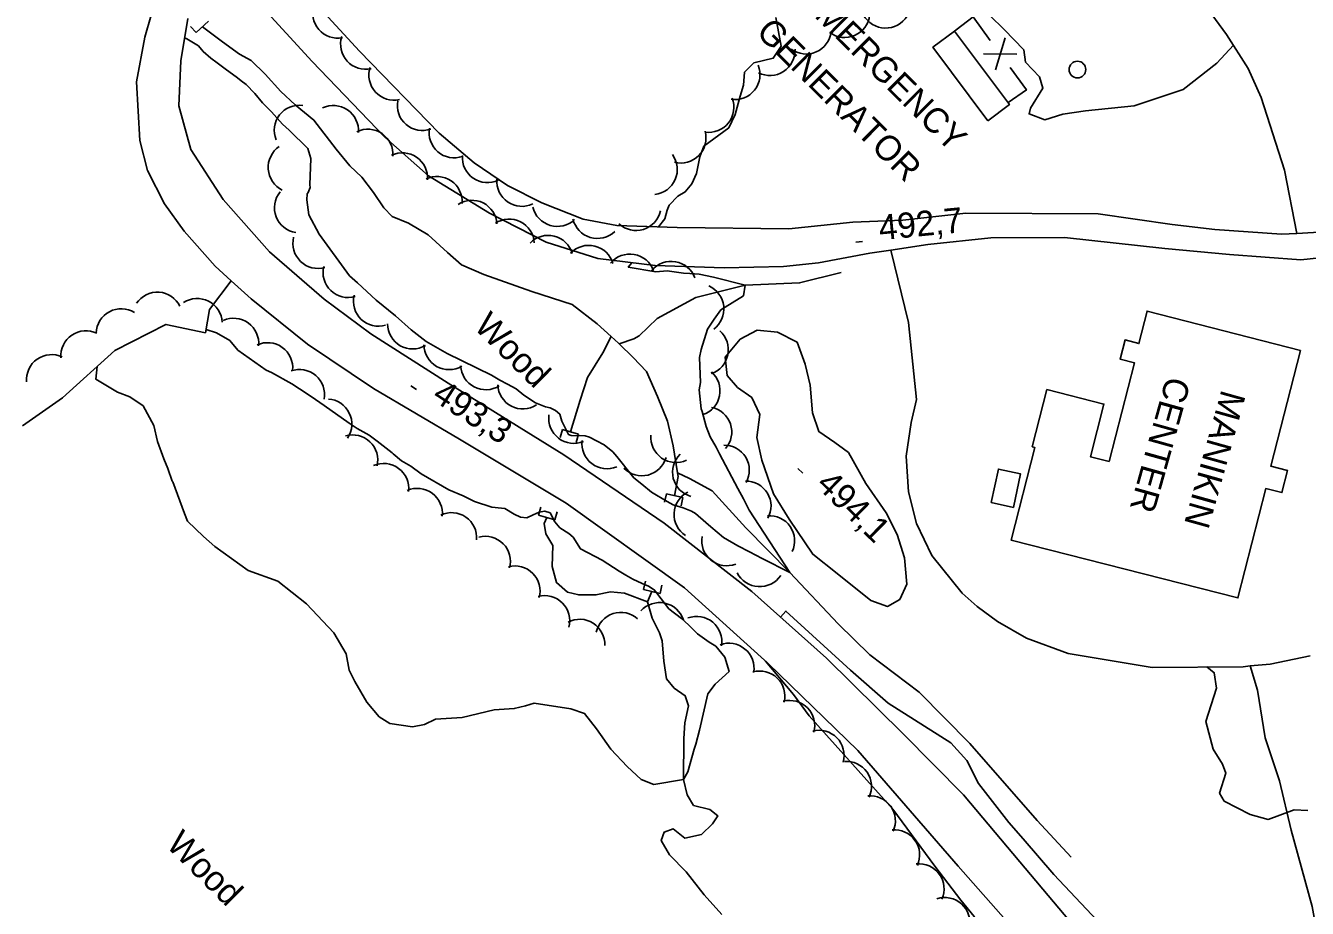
# Model space of a CAD drawing. Extents: x 642515 to 647219, y 6080136 to 6084356.
# Drawn here: x 643425.9 to 643579, y 6081671 to 6081776.4 of the extents above; entities that cross this region are included whole.
import ezdxf

# ---------------------------------------------------------------- set-up
doc = ezdxf.new("R2010")
doc.units = 0
for name, color, linetype in [('Level 19', 7, 'Continuous'), ('Level 2', 7, 'Continuous'), ('Level 21', 7, 'Continuous'), ('Level 22', 7, 'Continuous'), ('Level 26', 7, 'Continuous'), ('Level 3', 7, 'Continuous'), ('Level 31', 7, 'Continuous'), ('Level 36', 7, 'Continuous'), ('Level 37', 7, 'Continuous'), ('Level 4', 7, 'Continuous'), ('Level 44', 7, 'Continuous'), ('Level 52', 7, 'Continuous'), ('Level 57', 7, 'Continuous')]:
    doc.layers.add(name, color=color, linetype=linetype)

msp = doc.modelspace()

# ---------------------------------------------------------------- linework, layer by layer
at = {"layer": 'Level 19'}
msp.add_lwpolyline([(643577.69, 6081751.6), (643576.22, 6081759.16), (643573.43, 6081767.8), (643571.87, 6081771.28), (643569.31, 6081775.34), (643565.9, 6081779.99)], dxfattribs=at)
at = {"layer": 'Level 2'}
for points in [[(643570.12, 6081774.05), (643568.16, 6081771.91), (643564.14, 6081768.78), (643558.27, 6081766.82), (643552.46, 6081766.23), (643549.75, 6081765.81), (643547.58, 6081765.14), (643545.72, 6081765.86), (643545.88, 6081766.55), (643547.37, 6081768.95), (643546.96, 6081770.29), (643545.31, 6081772.04), (643545.09, 6081773.52), (643542.76, 6081775.94), (643541.04, 6081777.6), (643540.97, 6081780.46), (643542.26, 6081782.88), (643544.34, 6081785.52), (643547.63, 6081786.94), (643551.42, 6081787.48), (643553.06, 6081788.84), (643553.98, 6081790.75), (643552.03, 6081792.84), (643552.04, 6081793.47)], [(643515.48, 6081777.35), (643516.11, 6081773.93), (643515.16, 6081772.5), (643512.86, 6081771.95), (643511.73, 6081770.83), (643511.6, 6081769.29), (643511.2, 6081767.98), (643510.63, 6081765.77), (643509.85, 6081764.2), (643506.86, 6081761.99), (643506.38, 6081760.75), (643505.99, 6081758.76), (643505.43, 6081757.51), (643504.65, 6081756.54), (643503.76, 6081756.04), (643502.75, 6081754.96), (643502.51, 6081754.35), (643502.21, 6081753.32), (643501.48, 6081752.36)], [(643505.87, 6081718.17), (643505.41, 6081718.42), (643504.42, 6081718.84), (643503.23, 6081719.2), (643502.51, 6081719.6), (643500.63, 6081720.72), (643499.48, 6081721.65), (643498.5, 6081722.43), (643496.48, 6081724.95), (643496, 6081725.52), (643494.98, 6081726.34), (643494.06, 6081726.84), (643493.23, 6081727.27), (643492.69, 6081727.44), (643491.04, 6081727.45), (643490.71, 6081727.59), (643489.92, 6081729.18), (643489.66, 6081730.01), (643489.15, 6081730.46), (643488.52, 6081730.78), (643487.95, 6081730.9), (643486.76, 6081731.35), (643485.4, 6081732.3), (643484.47, 6081733.05), (643483.43, 6081733.58), (643482.51, 6081734.08), (643481.5, 6081734.66), (643476.22, 6081737.25), (643473.71, 6081738.69), (643471.92, 6081740.1), (643470.04, 6081741.75), (643467.75, 6081743.61), (643465.51, 6081745.71), (643464.57, 6081746.53), (643464.57, 6081746.53), (643464.57, 6081746.53), (643460.93, 6081751.51), (643459.7, 6081753.81), (643459.47, 6081755.6), (643459.5, 6081756.33), (643459.62, 6081756.46), (643459.86, 6081757.08), (643459.84, 6081757.4), (643459.96, 6081760.55), (643459.57, 6081761.73), (643457.34, 6081763.93), (643456.54, 6081764.65), (643455.24, 6081766.1), (643455.07, 6081766.25), (643454.17, 6081767.2), (643453.26, 6081768.31), (643452.23, 6081769.38), (643451.64, 6081769.82), (643451.18, 6081770.16), (643449.7, 6081771.24), (643448.74, 6081771.94), (643448.02, 6081772.5), (643447.09, 6081773.33), (643446.52, 6081773.98), (643445.15, 6081774.82), (643444.86, 6081774.93)], [(643498.26, 6081748.1), (643497.85, 6081747.57), (643501.15, 6081747.02), (643502.51, 6081747.11), (643504.46, 6081746.83), (643505.19, 6081746.8), (643506.32, 6081746.72), (643508.03, 6081746.35), (643511.81, 6081745.42), (643511.62, 6081744.16), (643508.92, 6081742.45), (643508.1, 6081741.35), (643507.3, 6081740.17), (643506.54, 6081737.75), (643506.36, 6081736.78), (643506.48, 6081733.81), (643506.3, 6081732.91), (643506.57, 6081730.64), (643506.68, 6081730.32), (643507.16, 6081728.54), (643507.64, 6081727.29), (643508.33, 6081726.09), (643508.75, 6081725.27), (643510.95, 6081721.15), (643511.6, 6081719.91), (643512.3, 6081718.55), (643517.13, 6081711.11), (643513.84, 6081712.78), (643512.34, 6081713.57), (643510.92, 6081714.28), (643509.24, 6081715.3), (643507.71, 6081716.56), (643507.11, 6081717.08), (643505.87, 6081718.17)], [(643494.74, 6081712.57), (643492.15, 6081713.93), (643491.26, 6081715.32), (643490.74, 6081715.77), (643489.69, 6081716.46), (643489.08, 6081717.15), (643488.52, 6081718.24), (643487.87, 6081718.44), (643487.23, 6081718.31), (643486.49, 6081717.98), (643485.75, 6081717.65), (643484.98, 6081717.72), (643484.23, 6081718.08), (643483.1, 6081718.76), (643482.73, 6081718.78), (643481.56, 6081718.9), (643479.5, 6081719.57), (643478.13, 6081720.25), (643476.43, 6081720.98), (643473.12, 6081722.89), (643471.89, 6081723.82), (643470.77, 6081724.43), (643469.78, 6081725.29), (643469.65, 6081725.4), (643467.87, 6081726.81), (643466.9, 6081727.51), (643465.48, 6081728.3), (643464.51, 6081728.92), (643461.55, 6081731.06), (643459.99, 6081732.12), (643458.6, 6081733.04), (643457.67, 6081733.62), (643455.25, 6081734.99), (643454.59, 6081735.26), (643454.59, 6081735.26), (643454.59, 6081735.26), (643451.23, 6081737.64), (643450.27, 6081738.79), (643448.69, 6081739.74), (643447.43, 6081740.14)], [(643524.16, 6081725.42), (643526.22, 6081721.73), (643528.67, 6081718.23), (643529.97, 6081715.65), (643530.84, 6081712.85), (643531.12, 6081709.72), (643530.28, 6081707.89), (643528.8, 6081707.07), (643526.82, 6081707.75), (643522.78, 6081710.98), (643519.89, 6081713.29), (643517.08, 6081717.49), (643515.18, 6081720.51), (643513.79, 6081724.53), (643513.21, 6081727.23), (643513.55, 6081729.96), (643512.61, 6081731.99), (643510.88, 6081733.2), (643509.66, 6081734.65), (643509.43, 6081736.81), (643511.22, 6081738.95), (643513.24, 6081740.05), (643515.68, 6081739.81), (643518.01, 6081738.59), (643518.99, 6081736), (643519.56, 6081733.46), (643519.86, 6081730.17), (643520.61, 6081727.93), (643522.51, 6081726.64), (643523.57, 6081725.87), (643524.16, 6081725.42)], [(643434.42, 6081735.7), (643434.27, 6081734.18), (643436.85, 6081732.65), (643438.33, 6081732.1), (643439.92, 6081730.99), (643441.19, 6081728.65), (643441.63, 6081726.74), (643442.4, 6081724.69)], [(643442.4, 6081724.69), (643442.88, 6081723.51), (643443.37, 6081722.01), (643443.46, 6081721.94), (643444.84, 6081718.17), (643445.23, 6081717.23), (643447.12, 6081715.42), (643448.49, 6081714.23), (643452.46, 6081711.35), (643456.01, 6081710.06), (643459.41, 6081707.39), (643462.7, 6081703.9), (643464.15, 6081701.42), (643464.53, 6081699.44), (643465.18, 6081698.11), (643466.64, 6081695.64), (643468.12, 6081693.88), (643469.38, 6081693.08), (643472.07, 6081692.7), (643473.5, 6081692.95), (643474.82, 6081693.6), (643478.03, 6081693.81), (643481.83, 6081694.71), (643484.23, 6081694.86), (643485.58, 6081695.19), (643486.6, 6081695.5), (643491, 6081694.83), (643492.64, 6081694.29), (643494.05, 6081692.45), (643495.78, 6081690.04), (643497.74, 6081687.95), (643499.41, 6081686.41), (643500.9, 6081685.79), (643504.45, 6081686.41), (643504.95, 6081687.33), (643505.73, 6081690.04), (643505.93, 6081690.61), (643506.34, 6081692.29), (643507.34, 6081696.62), (643508.23, 6081697.8), (643509.9, 6081699.28), (643509.38, 6081701.01), (643508.32, 6081702.31), (643507.53, 6081702.78), (643506.13, 6081703.78), (643505.05, 6081704.87), (643504.2, 6081705.62), (643502.71, 6081706.77), (643501.26, 6081708.64), (643500.95, 6081709.06), (643500.28, 6081709.5), (643499.53, 6081709.78), (643498.41, 6081710.31), (643497.57, 6081710.81), (643496.78, 6081711.28), (643494.74, 6081712.57)], [(643516.03, 6081705.77), (643516.68, 6081706.51), (643524.38, 6081699.47), (643528.91, 6081695.51), (643536.38, 6081690.78), (643538.29, 6081688.66), (643539.68, 6081685.94), (643543.29, 6081681.28), (643545.03, 6081679.31), (643548.69, 6081675.05), (643555.18, 6081668.17), (643560.81, 6081663.24), (643565.55, 6081658.49), (643567.75, 6081655.67), (643570.2, 6081652.78), (643571.85, 6081650.88), (643577.96, 6081643.73), (643578.78, 6081642.34), (643580.63, 6081639.89)], [(643579.83, 6081620.28), (643577.82, 6081622.63), (643575.54, 6081625.98), (643574.27, 6081627.54), (643569.86, 6081632.83), (643569.01, 6081634.02), (643566.8, 6081636.49), (643565.23, 6081638.23), (643562.6, 6081642.11), (643561.57, 6081643.69), (643559.77, 6081645.94), (643556.12, 6081650.04), (643552.74, 6081654.36), (643551.82, 6081656.06), (643545.8, 6081662.45), (643543.58, 6081665), (643542.62, 6081666.22), (643539.18, 6081670.05), (643537.57, 6081671.99), (643534.48, 6081676.04), (643529.44, 6081682.86), (643519.45, 6081694), (643517.59, 6081696.53), (643514.25, 6081700.52)], [(643578.99, 6081682.71), (643577.38, 6081682.77), (643574.27, 6081681.63), (643572.14, 6081682.22), (643569.01, 6081683.82), (643568.47, 6081684.75), (643569.2, 6081687.14), (643568.8, 6081688.24), (643567.72, 6081690.02), (643566.81, 6081693.31), (643568.12, 6081697.3), (643567.84, 6081699.14), (643566.93, 6081699.84)]]:
    msp.add_lwpolyline(points, dxfattribs=at)
at = {"layer": 'Level 21'}
for points in [[(643450.75, 6081789.66), (643465.75, 6081773.35), (643475.28, 6081763.56), (643479.45, 6081760.03), (643483.42, 6081757.31), (643487.51, 6081755.24), (643492.48, 6081753.31), (643496.49, 6081752.53), (643503.68, 6081752.28), (643517.01, 6081752.12), (643524.69, 6081752.95), (643530.65, 6081753.19), (643538.17, 6081754.01), (643553.96, 6081753.93), (643562.79, 6081752.67), (643567.91, 6081752.05), (643575.88, 6081751.49), (643577.69, 6081751.6), (643582.98, 6081751.92)], [(643450.8, 6081782.32), (643460.11, 6081772.11), (643468.79, 6081763.07), (643473.98, 6081758.47), (643481.29, 6081754.03), (643488.05, 6081750.53), (643494.23, 6081748.6), (643501.06, 6081747.76), (643509.31, 6081747.5), (643516.4, 6081747.65), (643520.56, 6081748.09), (643526.69, 6081749.22), (643529.21, 6081749.6), (643533.63, 6081750.25), (643541.15, 6081751.07), (643549.93, 6081751.09), (643561.93, 6081749.8), (643569.67, 6081749.06), (643578.17, 6081748.42), (643580.77, 6081748.71)], [(643598.04, 6081604.29), (643589.94, 6081613.58), (643580.56, 6081624.52), (643571.63, 6081635.29), (643560.4, 6081649.21), (643549.83, 6081661.79), (643537.25, 6081676.06), (643525.27, 6081689.88), (643514.56, 6081700.24), (643504.57, 6081709.29), (643490.45, 6081719.4), (643477.7, 6081727.01), (643467.43, 6081733.06), (643459.54, 6081738.38), (643452.81, 6081743.8), (643450.44, 6081745.94), (643448.51, 6081747.68), (643444.8, 6081751.87), (643442.47, 6081755.14), (643440.45, 6081759.12), (643439.51, 6081762.68), (643439.12, 6081769.69), (643440.12, 6081775.01), (643441.64, 6081780.33)], [(643588.5, 6081623.69), (643578.61, 6081636.21), (643571.26, 6081645.59), (643562, 6081656.05), (643554.58, 6081664.74), (643544.62, 6081676.56), (643537.89, 6081684.57), (643530.68, 6081691.86), (643521.51, 6081700.88), (643512.6, 6081708.84), (643502.15, 6081717.01), (643490.16, 6081725.16), (643476.34, 6081733.72), (643467.12, 6081739.6), (643461.53, 6081743.75), (643454.99, 6081749.38), (643449.46, 6081755.64), (643445.63, 6081761.6), (643444.19, 6081766.81), (643444.42, 6081772.21), (643445.24, 6081777.24)]]:
    msp.add_lwpolyline(points, dxfattribs=at)
at = {"layer": 'Level 22'}
msp.add_lwpolyline([(643572.13, 6081699.95), (643572.99, 6081697.08), (643573.9, 6081691.36), (643575.61, 6081686.25), (643577.01, 6081680.36), (643579.52, 6081671.24), (643581.11, 6081662.47), (643581.58, 6081659.73), (643581.92, 6081656.24), (643583.1, 6081650.35), (643584.4, 6081645.89), (643585.19, 6081642.61), (643587.16, 6081637.49), (643588.89, 6081633.69), (643589.6, 6081631.48), (643589.91, 6081628.09), (643590.6, 6081623.79), (643590.79, 6081620.7)], dxfattribs=at)
at = {"layer": 'Level 26'}
for p, q in [((643446.23, 6081775.56), (643445.57, 6081776.3)), ((643447.73, 6081776.92), (643446.23, 6081775.56)), ((643489.98, 6081728.19), (643489.7, 6081727.23)), ((643489.98, 6081728.19), (643491.92, 6081727.61)), ((643491.92, 6081727.61), (643491.62, 6081726.65)), ((643502.4, 6081720.49), (643502.18, 6081719.51)), ((643502.4, 6081720.49), (643504.38, 6081720.05)), ((643504.38, 6081720.05), (643504.16, 6081719.07)), ((643487.13, 6081717.96), (643487.41, 6081718.92)), ((643489.07, 6081717.4), (643487.13, 6081717.96)), ((643489.07, 6081717.4), (643489.35, 6081718.36)), ((643499.67, 6081709.1), (643499.91, 6081710.08)), ((643501.65, 6081708.62), (643499.67, 6081709.1)), ((643501.65, 6081708.62), (643501.87, 6081709.6))]:
    msp.add_line(p, q, dxfattribs=at)
at = {"layer": 'Level 3'}
for p, q in [((643525.03, 6081750.54), (643525.83, 6081750.62)), ((643471.88, 6081733.38), (643472.55, 6081732.94)), ((643518.12, 6081723.52), (643518.69, 6081722.96))]:
    msp.add_line(p, q, dxfattribs=at)
at = {"layer": 'Level 31'}
for points in [[(643540.8, 6081765.05), (643534.23, 6081773.82), (643536.81, 6081775.75), (643543.38, 6081766.98), (643540.8, 6081765.05)], [(643578.13, 6081737.63), (643574.59, 6081723.79), (643576.59, 6081723.27), (643575.92, 6081720.65), (643573.99, 6081721.14), (643570.65, 6081708.07), (643543.57, 6081714.99), (643546.4, 6081726.04), (643546.1, 6081726.12), (643547.85, 6081732.95), (643554.65, 6081731.21), (643553.04, 6081724.94), (643555.28, 6081724.37), (643558.29, 6081736.15), (643556.59, 6081736.58), (643557.18, 6081738.87), (643558.83, 6081738.44), (643559.82, 6081742.32), (643578.13, 6081737.63)], [(643541.19, 6081719.46), (643542.05, 6081723.46), (643544.7, 6081722.89), (643543.84, 6081718.89), (643541.19, 6081719.46)]]:
    msp.add_lwpolyline(points, dxfattribs=at)
at = {"layer": 'Level 36'}
msp.add_circle((643551.49, 6081771.15), 1, dxfattribs=at)
at = {"layer": 'Level 37'}
for p, q in [((643537.01, 6081775.89), (643536.82, 6081775.74)), ((643541.69, 6081771.11), (643542.85, 6081774.94)), ((643540.27, 6081773.05), (643544.27, 6081773))]:
    msp.add_line(p, q, dxfattribs=at)
for points in [[(643541.08, 6081774.64), (643539.03, 6081777.43), (643537.01, 6081775.89)], [(643543.21, 6081767.21), (643545.41, 6081768.73), (643543.44, 6081771.41)]]:
    msp.add_lwpolyline(points, dxfattribs=at)
at = {"layer": 'Level 4'}
for points in [[(643503.38, 6081720.27), (643503.8, 6081722.56), (643503.73, 6081723.02), (643503.23, 6081726.24), (643502.55, 6081729.18), (643501.35, 6081732.13), (643500.02, 6081735.11), (643498.45, 6081736.78), (643496.75, 6081738.43), (643496.69, 6081738.48), (643495.81, 6081739.28), (643494.15, 6081740.78), (643491.17, 6081743.09), (643486.34, 6081744.66), (643480.6, 6081746.67), (643477.93, 6081747.85), (643476.26, 6081749.32), (643473.94, 6081751.43), (643471.59, 6081752.81), (643469.64, 6081753.61), (643468.65, 6081754.64), (643467.41, 6081756.49), (643466.05, 6081758.3), (643464.6, 6081759.66), (643462.95, 6081761.65), (643460.32, 6081765.12), (643458.08, 6081766.95), (643456.37, 6081768.54), (643454.47, 6081770.6), (643452.8, 6081772.23), (643451.42, 6081772.99), (643449.4, 6081774.48), (643446.99, 6081776.24)], [(643523.26, 6081746.93), (643518.31, 6081745.68), (643511.81, 6081745.42), (643505.92, 6081743.94), (643501.3, 6081741.43), (643499.14, 6081739.35), (643498.5, 6081739), (643496.75, 6081738.43)], [(643495.81, 6081739.28), (643494.81, 6081737.35), (643492.99, 6081734.4), (643492.12, 6081731.68), (643490.94, 6081727.91)], [(643550.75, 6081677.11), (643546.67, 6081681.51), (643538.65, 6081690.7), (643532.61, 6081696.82), (643526.72, 6081701.29), (643522.93, 6081704.98), (643517.13, 6081711.11), (643511.9, 6081716.43), (643507.86, 6081720.87), (643505.17, 6081722.34), (643503.73, 6081723.02)], [(643500.14, 6081707.6), (643497.41, 6081708.63), (643495.74, 6081708.8), (643493.99, 6081708.44), (643491.93, 6081708.43), (643490.58, 6081708.78), (643489.29, 6081709.91), (643488.76, 6081711.81), (643488.84, 6081714.32), (643488.02, 6081715.72), (643487.82, 6081716.96), (643488.11, 6081717.68)], [(643509.01, 6081670.28), (643506.93, 6081672.65), (643504.77, 6081675.37), (643502.78, 6081677.42), (643501.78, 6081679.13), (643502.12, 6081680.12), (643503.22, 6081680.52), (643504.59, 6081679.4), (643506.58, 6081679.85), (643507.9, 6081681.11), (643508.53, 6081682.08), (643507.59, 6081682.83), (643505.66, 6081683.3), (643504.89, 6081684.58), (643504.45, 6081686.41), (643504.49, 6081691.3), (643504.6, 6081693.16), (643505.03, 6081695.21), (643504.63, 6081696.4), (643503.32, 6081697.32), (643502.4, 6081698.43), (643502.1, 6081700.51), (643501.9, 6081702.95), (643501.59, 6081703.9), (643500.71, 6081705.66), (643500.14, 6081707.6), (643500.67, 6081708.86)]]:
    msp.add_lwpolyline(points, dxfattribs=at)
at = {"layer": 'Level 44'}
for centre, start, end in [((643463.16, 6081777.9), 160.609, 280.587), ((643523.7, 6081777.98), 233.1867, 353.1646), ((643528.59, 6081779.1), 208.3336, 328.3115), ((643466.5, 6081774.19), 162.4889, 282.4668), ((643519.1, 6081776.01), 233.1867, 353.1646), ((643514.77, 6081773.44), 242.8499, 2.8278), ((643469.87, 6081770.5), 162.4889, 282.4668), ((643510.58, 6081770.57), 261.5586, 21.5365), ((643458.57, 6081763.9), 82.1652, 202.1431), ((643462.63, 6081763.86), 355.6182, 115.5962), ((643473.27, 6081766.88), 169.3353, 289.3132), ((643507.47, 6081766.65), 261.5586, 21.5365), ((643466.75, 6081761.03), 355.6182, 115.5962), ((643477.06, 6081763.62), 169.3353, 289.3132), ((643504.13, 6081762.99), 255.3408, 15.3188), ((643457.85, 6081759.47), 123.9464, 243.9244), ((643470.88, 6081758.21), 355.6182, 115.5962), ((643481.04, 6081760.65), 175.4802, 295.4582), ((643500.71, 6081759.23), 276.1894, 36.1674), ((643475.01, 6081755.39), 355.6817, 115.6596), ((643485.15, 6081757.82), 175.4802, 295.4582), ((643458.6, 6081754.66), 141.1461, 261.124), ((643479.17, 6081752.55), 3.2436, 123.2216), ((643489.38, 6081755.43), 193.3817, 313.3596), ((643483.63, 6081750.3), 3.2436, 123.2216), ((643494.17, 6081753.99), 193.3817, 313.3596), ((643498.77, 6081754.94), 227.3914, 347.3694), ((643460.8, 6081750.41), 166.0911, 286.069), ((643488.29, 6081748.36), 16.2785, 136.2565), ((643493.14, 6081747.17), 16.2785, 136.2565), ((643498.05, 6081746.12), 20.116, 140.0939), ((643464.4, 6081746.94), 166.0911, 286.069), ((643502.98, 6081745.26), 20.116, 140.0939), ((643506.27, 6081742.57), 306.552, 66.53), ((643441.62, 6081741.58), 26.2759, 146.2539), ((643446.37, 6081740.82), 3.1681, 123.1461), ((643468.02, 6081743.51), 166.5991, 286.5771), ((643437.3, 6081739.6), 58.0829, 178.0608), ((643450.72, 6081738.47), 354.2585, 114.2364), ((643472.11, 6081740.8), 180.4052, 300.3831), ((643433.09, 6081736.97), 64.2499, 184.2278), ((643506.8, 6081737.7), 288.5681, 48.5461), ((643454.78, 6081735.55), 354.2585, 114.2364), ((643476.45, 6081738.33), 180.4052, 300.3831), ((643428.99, 6081734.13), 65.2389, 185.2169), ((643458.58, 6081732.35), 349.5874, 109.5653), ((643480.83, 6081735.93), 182.6715, 302.6494), ((643505.81, 6081732.8), 288.5681, 48.5461), ((643485.27, 6081733.64), 182.6715, 302.6494), ((643461.84, 6081728.83), 326.1638, 86.1417), ((643507.21, 6081727.89), 318.4816, 78.4595), ((643491.35, 6081729.53), 172.5637, 292.5416), ((643464.93, 6081724.54), 346.4358, 106.4137), ((643503.55, 6081727.24), 175.191, 295.1689), ((643495.32, 6081726.49), 172.5637, 292.5416), ((643509.31, 6081723.31), 331.1765, 91.1544), ((643468.64, 6081721.13), 353.6579, 113.6358), ((643499.48, 6081725.66), 224.2014, 344.1794), ((643506.14, 6081723.08), 134.2199, 254.1978), ((643472.66, 6081718.16), 353.6579, 113.6358), ((643511.9, 6081719.03), 331.1765, 91.1544), ((643506.32, 6081718.04), 117.0964, 237.0743), ((643476.75, 6081715.26), 355.6201, 115.5981), ((643514.72, 6081714.89), 334.7969, 94.7749), ((643480.79, 6081712.43), 344.9841, 104.962), ((643509.62, 6081714.92), 170.7655, 290.7434), ((643484.32, 6081708.89), 344.9841, 104.962), ((643513.55, 6081712.42), 206.5877, 326.5657), ((643487.86, 6081705.35), 344.9841, 104.962), ((643501.59, 6081704.52), 18.1185, 138.0965), ((643492.05, 6081702.53), 357.4752, 117.4532), ((643496.97, 6081703.35), 48.0916, 168.0696), ((643506.02, 6081702.87), 350.298, 110.276), ((643509.87, 6081699.67), 350.298, 110.276), ((643513.56, 6081696.35), 346.0091, 105.987), ((643517.12, 6081692.84), 344.6125, 104.5905), ((643520.63, 6081689.28), 344.6125, 104.5905), ((643523.9, 6081685.57), 334.6168, 94.5948), ((643526.75, 6081681.46), 335.559, 95.537), ((643529.65, 6081677.39), 335.559, 95.537), ((643532.57, 6081673.33), 336.1765, 96.1545), ((643535.64, 6081669.31), 348.1067, 108.0846)]:
    msp.add_arc(centre, 3, start, end, dxfattribs=at)
at = {"layer": 'Level 52'}
msp.add_lwpolyline([(643529.21, 6081749.6), (643531.31, 6081740.95), (643532.28, 6081731.78), (643531.62, 6081729.03), (643531.04, 6081725.01), (643531.32, 6081720.75), (643532.26, 6081716.98), (643534.12, 6081713.16), (643537.72, 6081708.64), (643539.52, 6081707.07), (643541.93, 6081705.25), (643545.41, 6081703.27), (643550.4, 6081701.46), (643560.42, 6081699.79), (643571.29, 6081699.87), (643572.13, 6081699.95), (643574.5, 6081700.16), (643579.3, 6081701.17)], dxfattribs=at)
at = {"layer": 'Level 57'}
msp.add_lwpolyline([(643425.52, 6081728.61), (643430.3, 6081731.95), (643436.55, 6081737.63), (643442.63, 6081740.73), (643447.36, 6081739.73), (643447.84, 6081742.49), (643450.44, 6081745.94)], dxfattribs=at)

# ---------------------------------------------------------------- texts
at = {"layer": 'Level 3'}
for s, rotation, p in [('492,7', 5.5097, (643527.9, 6081750.78)), ('493,3', 327.0065, (643474.27, 6081731.78)), ('494,1', 315.59, (643520.15, 6081721.47))]:
    msp.add_text(s, height=3, rotation=rotation, dxfattribs=at).set_placement(p)
at = {"layer": 'Level 31'}
for s, rotation, p in [('EMERGENCY', 315.175, (643518.09, 6081779.39)), ('GENERATOR', 315.175, (643512.99, 6081775.48)), ('CENTER', 254.3808, (643562.16, 6081734.67)), ('MANIKIN', 254.3808, (643568.72, 6081733.05)), ('MANIKIN', 254.3808, (643568.72, 6081733.05))]:
    msp.add_text(s, height=3, rotation=rotation, dxfattribs=at).set_placement(p)
at = {"layer": 'Level 44'}
for p in [(643479.28, 6081740.33), (643442.53, 6081678.47)]:
    msp.add_text('Wood', height=3, rotation=315.1749, dxfattribs=at).set_placement(p)

doc.saveas('drawing.dxf')
